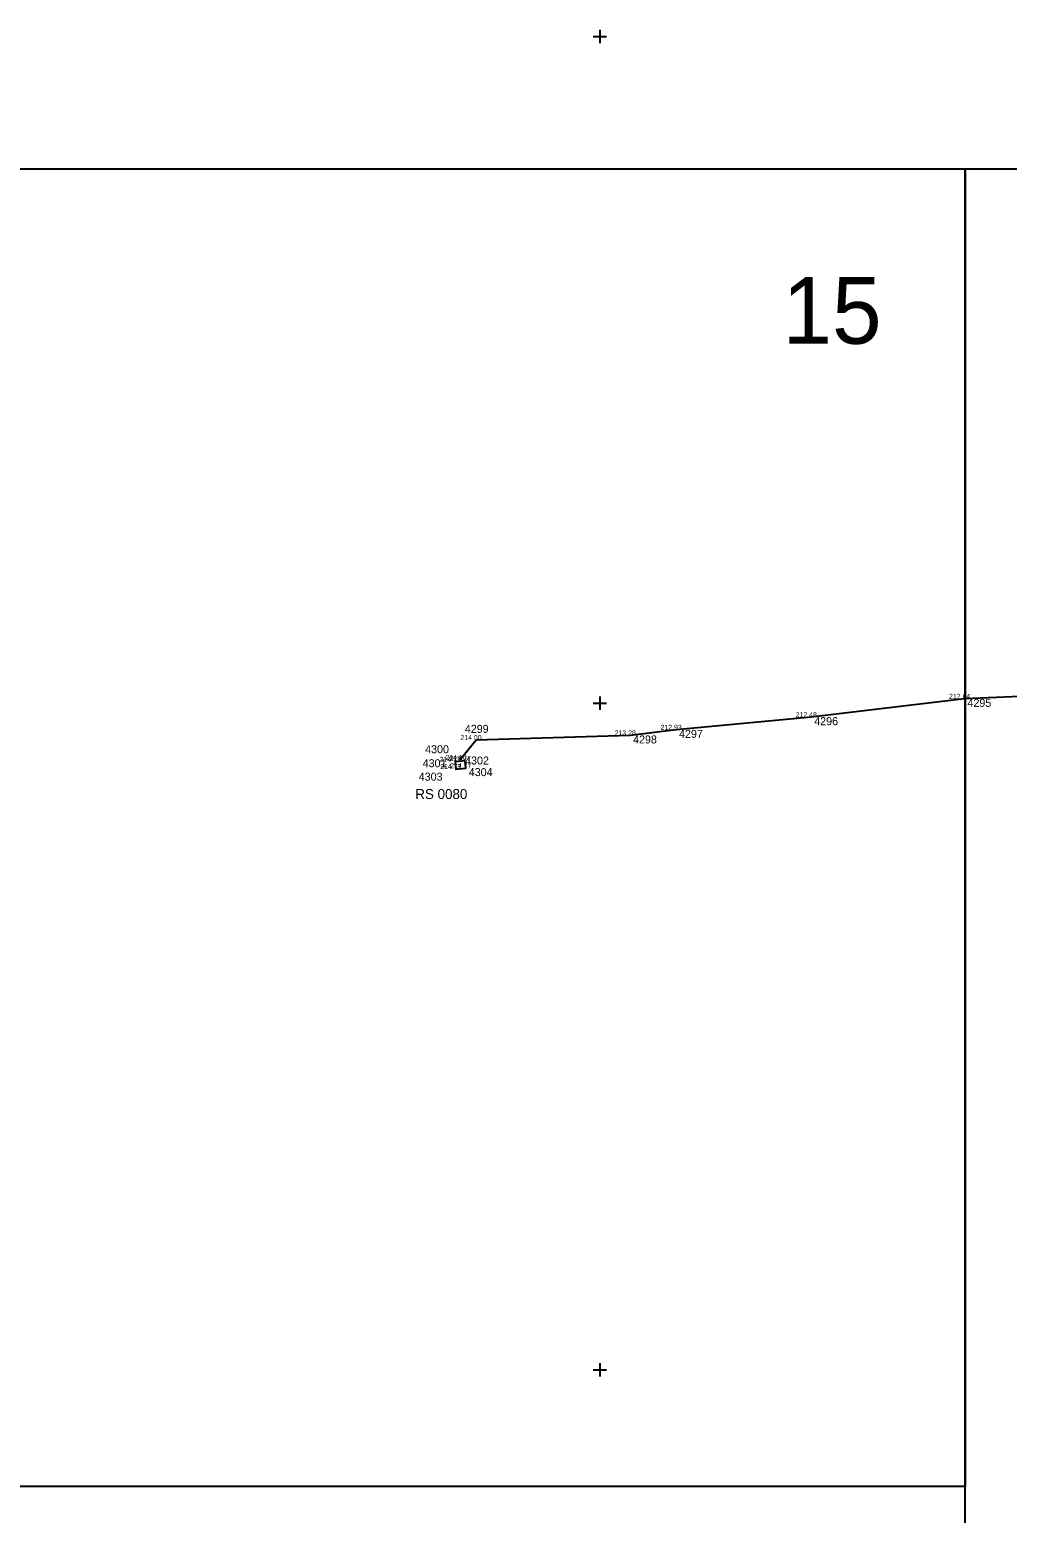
# Model space of a CAD drawing. Extents: x -736532 to -730799, y -1045301 to -1042399.
# Drawn here: x -736385.5 to -736238.9, y -1042621.5 to -1042399 of the extents above; entities that cross this region are included whole.
import ezdxf

# ---------------------------------------------------------------- set-up
doc = ezdxf.new("R2010")
doc.units = 0
for name, color, linetype in [('Vrstva 23', 7, 'Continuous'), ('Vrstva 25', 7, 'Continuous'), ('Vrstva 26', 7, 'Continuous'), ('Vrstva 60', 7, 'Continuous'), ('Vrstva 61', 7, 'Continuous'), ('Vrstva 62', 7, 'Continuous'), ('Vrstva 63', 7, 'Continuous')]:
    doc.layers.add(name, color=color, linetype=linetype)

msp = doc.modelspace()

# ---------------------------------------------------------------- linework, layer by layer
at = {"layer": 'Vrstva 23'}
msp.add_lwpolyline([(-736320.16, -1042508.67), (-736321.66, -1042508.81), (-736321.59, -1042509.9), (-736320.08, -1042509.77), (-736320.16, -1042508.67)], dxfattribs=at)
at = {"layer": 'Vrstva 26'}
for points in [[(-736233.38, -1042498.86), (-736245.32, -1042499.37), (-736268.29, -1042502.12), (-736288.56, -1042504.02), (-736295.45, -1042504.86), (-736318.55, -1042505.56), (-736320.93, -1042508.54)], [(-736295.45, -1042504.86), (-736318.55, -1042505.56), (-736320.93, -1042508.54)]]:
    msp.add_lwpolyline(points, dxfattribs=at)
at = {"layer": 'Vrstva 60'}
for p, q in [((-736245.32, -1042499.37), (-736245.32, -1042499.37)), ((-736268.29, -1042502.12), (-736268.29, -1042502.12)), ((-736295.45, -1042504.86), (-736295.45, -1042504.86)), ((-736288.56, -1042504.02), (-736288.56, -1042504.02)), ((-736318.55, -1042505.56), (-736318.55, -1042505.56)), ((-736321.66, -1042508.81), (-736321.66, -1042508.81)), ((-736320.93, -1042508.54), (-736320.93, -1042508.54)), ((-736320.16, -1042508.67), (-736320.16, -1042508.67)), ((-736321.59, -1042509.9), (-736321.59, -1042509.9)), ((-736320.08, -1042509.77), (-736320.08, -1042509.77))]:
    msp.add_line(p, q, dxfattribs=at)
at = {"layer": 'Vrstva 61'}
for p, q in [((-736301, -1042400), (-736299, -1042400)), ((-736300, -1042399), (-736300, -1042401)), ((-736301, -1042500), (-736299, -1042500)), ((-736300, -1042499), (-736300, -1042501)), ((-736301, -1042600), (-736299, -1042600)), ((-736300, -1042599), (-736300, -1042601))]:
    msp.add_line(p, q, dxfattribs=at)
at = {"layer": 'Vrstva 63'}
for points in [[(-736532.01, -1042419.88), (-736245.2, -1042419.88), (-736245.2, -1042617.52), (-736532.01, -1042617.52)], [(-736245.2, -1042419.88), (-735841.08, -1042419.88), (-735841.08, -1042698.84), (-736245.2, -1042698.84)]]:
    msp.add_lwpolyline(points, close=True, dxfattribs=at)

# ---------------------------------------------------------------- texts
at = {"layer": 'Vrstva 25'}
msp.add_text('RS 0080', height=1.5, dxfattribs=at).set_placement((-736327.65, -1042514.4))
at = {"layer": 'Vrstva 61'}
for s, p in [(' 4295', (-736245.32, -1042500.57)), (' 4296', (-736268.29, -1042503.32)), (' 4299', (-736320.67, -1042504.47)), (' 4298', (-736295.45, -1042506.06)), (' 4297', (-736288.56, -1042505.22)), (' 4300', (-736326.62, -1042507.53)), (' 4301', (-736326.99, -1042509.63)), (' 4302', (-736320.63, -1042509.22)), (' 4303', (-736327.58, -1042511.64)), (' 4304', (-736320.08, -1042510.96))]:
    msp.add_text(s, height=1.2, dxfattribs=at).set_placement(p)
at = {"layer": 'Vrstva 62'}
for s, p in [('212 64 ', (-736247.64, -1042499.37)), ('212 48 ', (-736270.62, -1042502.12)), ('214 00 ', (-736320.88, -1042505.56)), ('213 28 ', (-736297.76, -1042504.86)), ('212 93 ', (-736290.88, -1042504.02)), ('214 77 ', (-736324, -1042508.81)), ('214 77 ', (-736323.92, -1042509.9)), ('214 10 ', (-736323.13, -1042508.54)), ('214 77 ', (-736322.49, -1042508.67)), ('214 77 ', (-736322.41, -1042509.77))]:
    msp.add_text(s, height=0.75, dxfattribs=at).set_placement(p)
at = {"layer": 'Vrstva 63'}
msp.add_text('15', height=10, dxfattribs=at).set_placement((-736272.62, -1042446.11))

doc.saveas('drawing.dxf')
